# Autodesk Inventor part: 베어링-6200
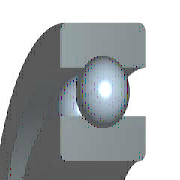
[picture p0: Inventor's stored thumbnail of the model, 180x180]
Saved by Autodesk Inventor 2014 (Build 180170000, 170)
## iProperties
Created: 2012-02
Part Number: 베어링-6200
Material: 강철, 연강
Description: 깊은 그루브 볼 베어링
Document SubType Name: Modeling
Standard: KS B 2023
Designer: mduedu
Standards Organization: KS
Language: ko-KR
Size Designation: 6200 - 10 x 30 x 9
Categories: <MemberInstance><Categories><Category DisplayName="샤프트 부품" InternalName="7f7aeb1f-a693-4053-b835-cee3144e0d98" Mnemonic="SHFT"><Category DisplayName="베어링" Inter
Density: 1 g/cm^3
Appearance: 노란색
IsCustomPart: 1
Author: mduedu
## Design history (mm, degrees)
sketch "스케치" dims "d0" = 5.2 (= -0.26 x WD + 0.26 x BD)
  geometry: L1 (1.9, 10)-(7.1, 10); L2 (4.5, 10)-(4.5, 7.4); L3 (4.5, 10)-(4.5, 12.6); L4 (2.568, 8.26)-(0, 8.26); L5 (0, 5)-(9, 5); L6 (2.568, 11.74)-(0, 11.74); L7 (0, 15)-(9, 15); L8 (9, 5)-(9, 8.26); L9 (6.432, 8.26)-(9, 8.26); L10 (6.432, 11.74)-(9, 11.74); L11 (9, 15)-(9, 11.74); L12 (-1.4, 0)-(8.4, 0) reference; L13 (0, -0.3)-(0, 5.3) reference
  constraints: 22 end point, 4 point on line, 2 collinear, 2 perpendicular, 2 symmetric about line, 1 midpoint, 1 parallel, 14 other
  dimensions: "d9" = 10 diameter of L5 L12 (= WD); "d11" = 30 diameter of L7 L12 (= BD); "d12" = 9 distance between parallel lines of L8 L13 (= KB); "d13" = 16.52 diameter of L9 L12 (= 0.326 x BD + 0.674 x WD)
revolve "본체" stored, may be unused: angle "d6" = 90 deg
revolve "볼" stored, may be unused: angle "d7" = 90 deg
pattern_circular "IDS_ARRAYBALL[SIMPL:T]" dims angle "d3" = 360 deg
body "Solid1"
fillet "모깎기1" dims "d1" = 0.6 (= KRS)
other parameters: "WD" = 10 [user parameter; used in 5 equation terms], "BD" = 30 [user parameter; used in 5 equation terms], "KB" = 9 [user parameter; used in 1 equation term], "KRS" = 0.6 [user parameter; used in 1 equation term], "d4" = 0, "d5" = 0, "d8" = 0, "d14" = 0, "d15" = 0, "BBA" = 0 [user parameter], "BC0" = 2360000 [user parameter], "BC" = 5070000 [user parameter], "BR" = 15 (= 0.5 x BD) [user parameter], "WR" = 5 (= 0.5 x WD) [user parameter]
